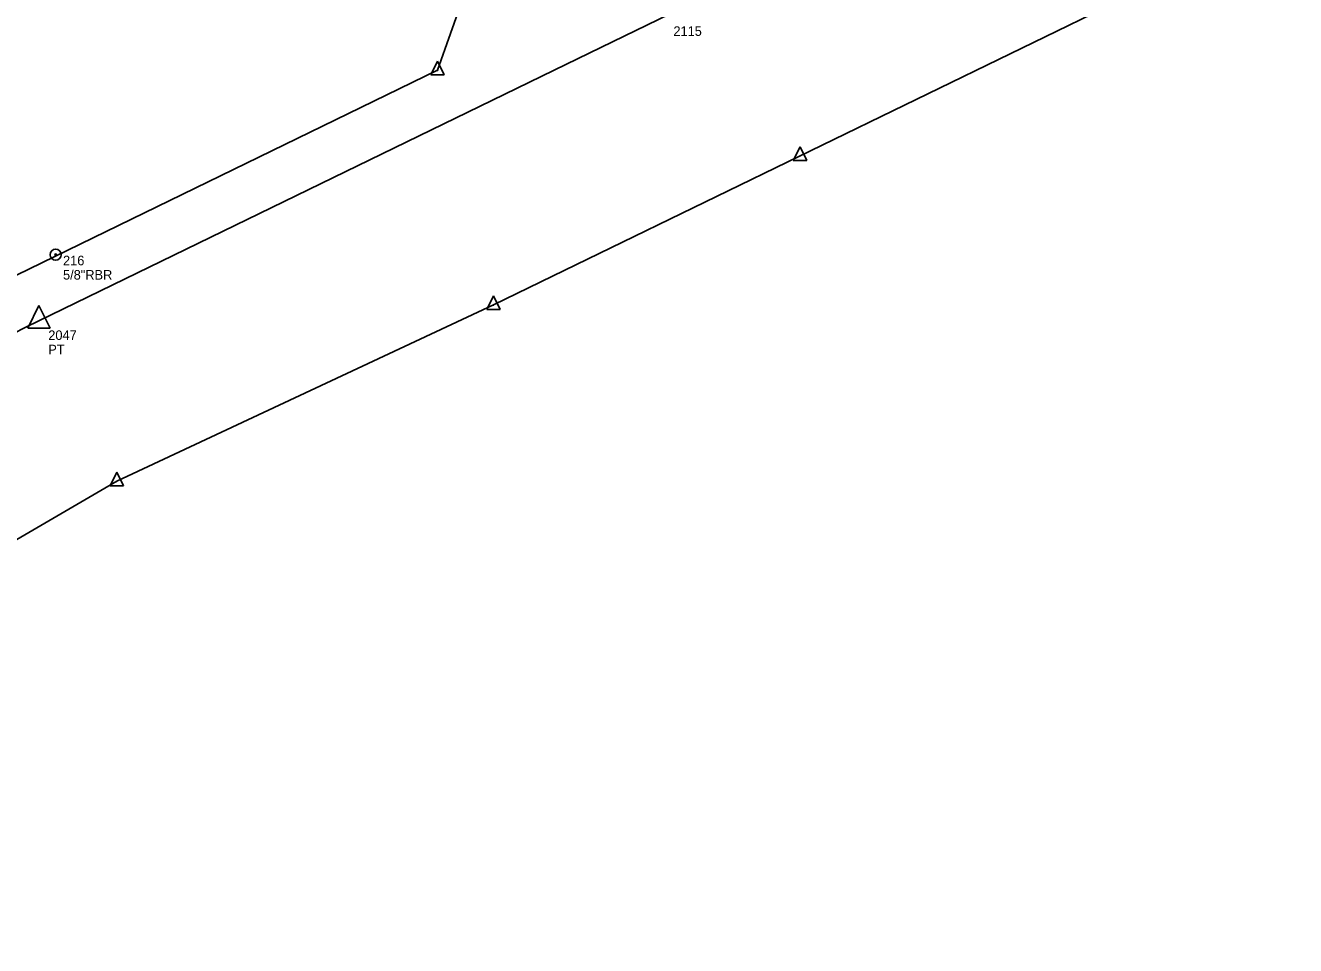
# Model space of a CAD drawing. Extents: x 1674300 to 1677920, y 225056 to 231852.
# Drawn here: x 1675417 to 1676414, y 226643 to 227365 of the extents above; entities that cross this region are included whole.
import ezdxf

# ---------------------------------------------------------------- set-up
doc = ezdxf.new("R2010")
doc.units = 0
for name, color, linetype in [('S_CAL_CORNER', 7, 'Continuous'), ('S_CAL_CORNER_ANNOT', 7, 'Continuous'), ('S_EXIST_ROW', 7, 'Continuous'), ('S_EXISTING_ALIGNMENT', 7, 'Continuous'), ('S_IRON_PIN', 7, 'Continuous'), ('S_IRON_PIN_ANNOT', 7, 'Continuous')]:
    doc.layers.add(name, color=color, linetype=linetype)

msp = doc.modelspace()

# ---------------------------------------------------------------- linework, layer by layer
at = {"layer": 'S_CAL_CORNER'}
for p, q in [((1675427.62, 227145.4), (1675418.8, 227127.67)), ((1675427.62, 227145.4), (1675418.8, 227127.67)), ((1675427.62, 227145.4), (1675436.34, 227127.67)), ((1675427.62, 227145.4), (1675436.34, 227127.67)), ((1675418.8, 227127.67), (1675436.34, 227127.67)), ((1675418.8, 227127.67), (1675436.34, 227127.67))]:
    msp.add_line(p, q, dxfattribs=at)
at = {"layer": 'S_EXIST_ROW'}
for p, q in [((1675784.51, 227145.88), (1676413.97, 227452.12)), ((1675740.53, 227330.21), (1675775.31, 227429.27)), ((1675740.54, 227337.31), (1675735.26, 227326.67)), ((1675740.54, 227337.31), (1675745.78, 227326.67)), ((1675409.98, 227169.4), (1675740.53, 227330.21)), ((1675735.26, 227326.67), (1675745.78, 227326.67)), ((1675740.53, 227330.21), (1675740.53, 227330.21)), ((1676025.03, 227269.98), (1676019.74, 227259.34)), ((1676025.03, 227269.98), (1676030.26, 227259.34)), ((1676019.74, 227259.34), (1676030.26, 227259.34)), ((1676025.01, 227262.89), (1676025.01, 227262.89)), ((1675488.73, 227007.54), (1675784.51, 227145.88)), ((1675784.53, 227152.97), (1675779.24, 227142.33)), ((1675784.51, 227145.88), (1675784.51, 227145.88)), ((1675784.53, 227152.97), (1675789.76, 227142.33)), ((1675779.24, 227142.33), (1675789.76, 227142.33)), ((1675357, 226930.8), (1675488.73, 227007.54)), ((1675488.75, 227014.63), (1675483.46, 227003.99)), ((1675488.73, 227007.54), (1675488.73, 227007.54)), ((1675488.75, 227014.63), (1675493.98, 227003.99)), ((1675483.46, 227003.99), (1675493.98, 227003.99))]:
    msp.add_line(p, q, dxfattribs=at)
for centre, radius in [((1675740.53, 227330.21), 0.18), ((1675740.53, 227330.21), 0.09), ((1676025.01, 227262.89), 0.18), ((1676025.01, 227262.89), 0.09), ((1675784.51, 227145.88), 0.18), ((1675784.51, 227145.88), 0.09), ((1675488.73, 227007.54), 0.18), ((1675488.73, 227007.54), 0.09)]:
    msp.add_circle(centre, radius, dxfattribs=at)
at = {"layer": 'S_EXISTING_ALIGNMENT'}
for p, q in [((1675841.07, 227334.65), (1676112.44, 227466.67)), ((1675427.48, 227133.43), (1675841.07, 227334.65))]:
    msp.add_line(p, q, dxfattribs=at)
msp.add_arc((1675935.58, 226089.07), 1161.4, 115.94359, 151.51603, dxfattribs=at)
at = {"layer": 'S_IRON_PIN'}
for radius in [4.36, 0.617, 0.392, 0.317, 0.218, 0.123, 0.0872]:
    msp.add_circle((1675440.76, 227185.37), radius, dxfattribs=at)

# ---------------------------------------------------------------- texts
at = {"layer": 'S_CAL_CORNER_ANNOT'}
for s, p in [('2115', (1675925.63, 227357.14)), ('2047', (1675434.98, 227118.43)), ('2047', (1675434.98, 227118.43)), ('PT', (1675434.98, 227107.18)), ('PT', (1675434.98, 227107.18))]:
    msp.add_text(s, height=7.5, rotation=360, dxfattribs=at).set_placement(p)
at = {"layer": 'S_IRON_PIN_ANNOT'}
for s, p in [('216', (1675446.55, 227177.06)), ('5/8"RBR ', (1675446.55, 227165.81))]:
    msp.add_text(s, height=7.5, rotation=360, dxfattribs=at).set_placement(p)

doc.saveas('drawing.dxf')
